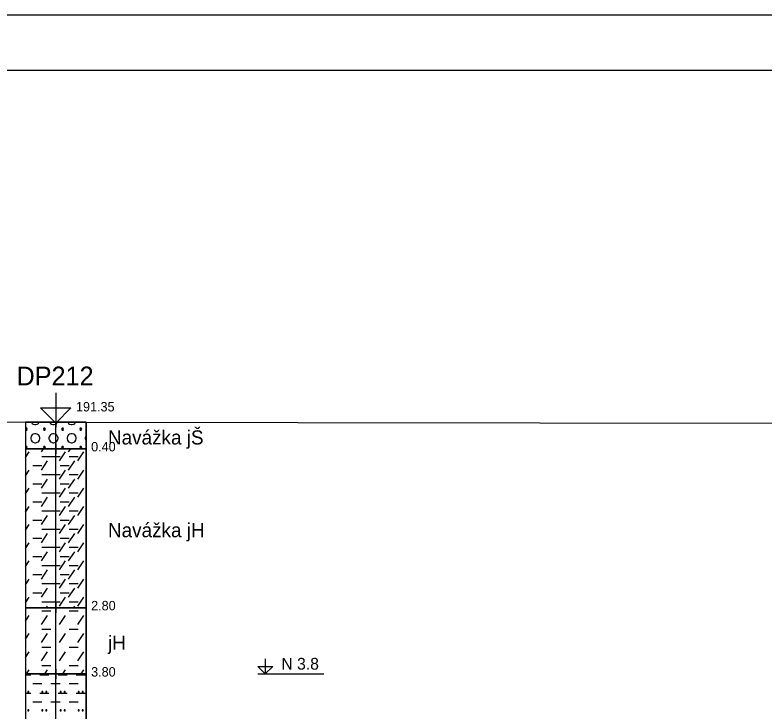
# Model space of a CAD drawing. Extents: x 3042 to 4120, y 576 to 2694.
# Drawn here: x 3879.6 to 3936.1, y 1352.3 to 1404.8 of the extents above; entities that cross this region are included whole.
import ezdxf

# ---------------------------------------------------------------- set-up
doc = ezdxf.new("R2010")
doc.units = 0
for name, color, linetype in [('1', 7, 'Continuous'), ('11', 7, 'Continuous'), ('15', 7, 'Continuous'), ('16', 7, 'Continuous'), ('17', 7, 'Continuous'), ('18', 7, 'Continuous'), ('51', 7, 'Continuous'), ('52', 7, 'Continuous'), ('53', 7, 'Continuous'), ('56', 7, 'Continuous'), ('61', 7, 'Continuous')]:
    doc.layers.add(name, color=color, linetype=linetype)

msp = doc.modelspace()

# ---------------------------------------------------------------- linework, layer by layer
at = {"layer": '1'}
for points in [[(3752.823, 1404.813), (4067.823, 1404.813), (4067.823, 1299.813), (3752.823, 1299.813), (3752.823, 1404.813)], [(3757.014, 1304.004), (4063.632, 1304.004), (4063.632, 1400.622), (3757.014, 1400.622), (3757.014, 1304.004)]]:
    msp.add_lwpolyline(points, dxfattribs=at)
at = {"layer": '11'}
for p, q in [((3831.333, 1374.363), (3882.673, 1374.063)), ((3882.673, 1374.063), (3955.713, 1373.963))]:
    msp.add_line(p, q, dxfattribs=at)
at = {"layer": '15'}
msp.add_lwpolyline([(3882.673, 1376.286), (3882.673, 1374), (3881.53, 1375.143), (3883.816, 1375.143), (3882.673, 1374)], dxfattribs=at)
at = {"layer": '18'}
msp.add_line((3882.673, 1327.313), (3882.673, 1374.063), dxfattribs=at)
at = {"layer": '51'}
for points in [[(3880.387, 1372.063), (3884.959, 1372.063), (3884.959, 1374.063), (3880.387, 1374.063)], [(3880.387, 1360.063), (3884.959, 1360.063), (3884.959, 1372.063), (3880.387, 1372.063)], [(3880.387, 1355.063), (3884.959, 1355.063), (3884.959, 1360.063), (3880.387, 1360.063)], [(3880.387, 1347.063), (3884.959, 1347.063), (3884.959, 1355.063), (3880.387, 1355.063)]]:
    msp.add_lwpolyline(points, close=True, dxfattribs=at)
for points in [[(3880.83, 1374.063), (3880.898, 1373.96), (3880.974, 1373.922), (3881.089, 1373.884), (3881.165, 1373.884), (3881.279, 1373.922), (3881.355, 1373.96), (3881.424, 1374.063)], [(3882.201, 1374.063), (3882.27, 1373.96), (3882.346, 1373.922), (3882.46, 1373.884), (3882.537, 1373.884), (3882.651, 1373.922), (3882.727, 1373.96), (3882.796, 1374.063)], [(3883.573, 1374.063), (3883.641, 1373.96), (3883.718, 1373.922), (3883.832, 1373.884), (3883.908, 1373.884), (3884.022, 1373.922), (3884.099, 1373.96), (3884.167, 1374.063)], [(3880.403, 1373.617), (3880.387, 1373.585)], [(3880.387, 1373.497), (3880.403, 1373.465), (3880.479, 1373.465), (3880.517, 1373.541), (3880.479, 1373.617), (3880.403, 1373.617), (3880.479, 1373.465)], [(3881.089, 1373.198), (3880.974, 1373.16), (3880.898, 1373.122), (3880.822, 1373.008), (3880.784, 1372.893), (3880.784, 1372.817), (3880.822, 1372.703), (3880.898, 1372.589), (3880.974, 1372.55), (3881.089, 1372.512), (3881.165, 1372.512), (3881.279, 1372.55), (3881.355, 1372.589), (3881.432, 1372.703), (3881.47, 1372.817), (3881.47, 1372.893), (3881.432, 1373.008), (3881.355, 1373.122), (3881.279, 1373.16), (3881.165, 1373.198), (3881.089, 1373.198)], [(3881.775, 1373.617), (3881.736, 1373.541), (3881.775, 1373.465), (3881.851, 1373.465), (3881.889, 1373.541), (3881.851, 1373.617), (3881.775, 1373.617), (3881.851, 1373.465)], [(3882.46, 1373.198), (3882.346, 1373.16), (3882.27, 1373.122), (3882.194, 1373.008), (3882.156, 1372.893), (3882.156, 1372.817), (3882.194, 1372.703), (3882.27, 1372.589), (3882.346, 1372.55), (3882.46, 1372.512), (3882.537, 1372.512), (3882.651, 1372.55), (3882.727, 1372.589), (3882.803, 1372.703), (3882.841, 1372.817), (3882.841, 1372.893), (3882.803, 1373.008), (3882.727, 1373.122), (3882.651, 1373.16), (3882.537, 1373.198), (3882.46, 1373.198)], [(3883.146, 1373.617), (3883.108, 1373.541), (3883.146, 1373.465), (3883.222, 1373.465), (3883.26, 1373.541), (3883.222, 1373.617), (3883.146, 1373.617), (3883.222, 1373.465)], [(3883.832, 1373.198), (3883.718, 1373.16), (3883.641, 1373.122), (3883.565, 1373.008), (3883.527, 1372.893), (3883.527, 1372.817), (3883.565, 1372.703), (3883.641, 1372.589), (3883.718, 1372.55), (3883.832, 1372.512), (3883.908, 1372.512), (3884.022, 1372.55), (3884.099, 1372.589), (3884.175, 1372.703), (3884.213, 1372.817), (3884.213, 1372.893), (3884.175, 1373.008), (3884.099, 1373.122), (3884.022, 1373.16), (3883.908, 1373.198), (3883.832, 1373.198)], [(3884.518, 1373.617), (3884.48, 1373.541), (3884.518, 1373.465), (3884.594, 1373.465), (3884.632, 1373.541), (3884.594, 1373.617), (3884.518, 1373.617), (3884.594, 1373.465)], [(3884.959, 1373.041), (3884.937, 1373.008), (3884.899, 1372.893), (3884.899, 1372.817), (3884.937, 1372.703), (3884.959, 1372.67)], [(3880.403, 1372.246), (3880.387, 1372.214)], [(3880.387, 1372.125), (3880.403, 1372.093), (3880.479, 1372.093), (3880.517, 1372.169), (3880.479, 1372.246), (3880.403, 1372.246), (3880.479, 1372.093)], [(3881.584, 1371.827), (3881.742, 1372.063)], [(3881.775, 1372.246), (3881.736, 1372.169), (3881.775, 1372.093), (3881.851, 1372.093), (3881.889, 1372.169), (3881.851, 1372.246), (3881.775, 1372.246), (3881.851, 1372.093)], [(3883.146, 1372.246), (3883.108, 1372.169), (3883.146, 1372.093), (3883.222, 1372.093), (3883.26, 1372.169), (3883.222, 1372.246), (3883.146, 1372.246), (3883.222, 1372.093)], [(3883.641, 1371.827), (3883.799, 1372.063)], [(3884.518, 1372.246), (3884.48, 1372.169), (3884.518, 1372.093), (3884.594, 1372.093), (3884.632, 1372.169), (3884.594, 1372.246), (3884.518, 1372.246), (3884.594, 1372.093)], [(3880.387, 1371.403), (3880.67, 1371.827)], [(3881.622, 1371.484), (3882.308, 1371.484)], [(3882.308, 1371.484), (3882.994, 1371.484)], [(3882.956, 1371.141), (3883.413, 1371.827)], [(3883.68, 1371.484), (3884.365, 1371.484)], [(3884.327, 1371.141), (3884.784, 1371.827)], [(3881.584, 1370.455), (3882.041, 1371.141)], [(3883.641, 1370.455), (3884.099, 1371.141)], [(3880.387, 1370.031), (3880.67, 1370.455)], [(3880.936, 1370.798), (3881.622, 1370.798)], [(3882.956, 1369.769), (3883.413, 1370.455)], [(3882.994, 1370.798), (3883.68, 1370.798)], [(3884.327, 1369.769), (3884.784, 1370.455)], [(3881.584, 1369.083), (3882.041, 1369.769)], [(3881.622, 1370.112), (3882.308, 1370.112)], [(3882.308, 1370.112), (3882.994, 1370.112)], [(3883.641, 1369.083), (3884.099, 1369.769)], [(3883.68, 1370.112), (3884.365, 1370.112)], [(3880.936, 1369.426), (3881.622, 1369.426)], [(3882.994, 1369.426), (3883.68, 1369.426)], [(3880.387, 1368.659), (3880.67, 1369.083)], [(3881.622, 1368.74), (3882.308, 1368.74)], [(3882.308, 1368.74), (3882.994, 1368.74)], [(3882.956, 1368.398), (3883.413, 1369.083)], [(3883.68, 1368.74), (3884.365, 1368.74)], [(3884.327, 1368.398), (3884.784, 1369.083)], [(3880.936, 1368.055), (3881.622, 1368.055)], [(3881.584, 1367.712), (3882.041, 1368.398)], [(3882.994, 1368.055), (3883.68, 1368.055)], [(3883.641, 1367.712), (3884.099, 1368.398)], [(3880.387, 1367.288), (3880.67, 1367.712)], [(3882.956, 1367.026), (3883.413, 1367.712)], [(3884.327, 1367.026), (3884.784, 1367.712)], [(3881.584, 1366.34), (3882.041, 1367.026)], [(3881.622, 1367.369), (3882.308, 1367.369)], [(3882.308, 1367.369), (3882.994, 1367.369)], [(3883.641, 1366.34), (3884.099, 1367.026)], [(3883.68, 1367.369), (3884.365, 1367.369)], [(3880.936, 1366.683), (3881.622, 1366.683)], [(3882.994, 1366.683), (3883.68, 1366.683)], [(3880.387, 1365.916), (3880.67, 1366.34)], [(3881.622, 1365.997), (3882.308, 1365.997)], [(3882.308, 1365.997), (3882.994, 1365.997)], [(3882.956, 1365.654), (3883.413, 1366.34)], [(3883.68, 1365.997), (3884.365, 1365.997)], [(3884.327, 1365.654), (3884.784, 1366.34)], [(3880.936, 1365.311), (3881.622, 1365.311)], [(3881.584, 1364.969), (3882.041, 1365.654)], [(3882.994, 1365.311), (3883.68, 1365.311)], [(3883.641, 1364.969), (3884.099, 1365.654)], [(3880.387, 1364.545), (3880.67, 1364.969)], [(3882.956, 1364.283), (3883.413, 1364.969)], [(3884.327, 1364.283), (3884.784, 1364.969)], [(3881.584, 1363.597), (3882.041, 1364.283)], [(3881.622, 1364.626), (3882.308, 1364.626)], [(3882.308, 1364.626), (3882.994, 1364.626)], [(3883.641, 1363.597), (3884.099, 1364.283)], [(3883.68, 1364.626), (3884.365, 1364.626)], [(3880.387, 1363.173), (3880.67, 1363.597)], [(3880.936, 1363.94), (3881.622, 1363.94)], [(3882.956, 1362.911), (3883.413, 1363.597)], [(3882.994, 1363.94), (3883.68, 1363.94)], [(3884.327, 1362.911), (3884.784, 1363.597)], [(3881.622, 1363.254), (3882.308, 1363.254)], [(3882.308, 1363.254), (3882.994, 1363.254)], [(3883.68, 1363.254), (3884.365, 1363.254)], [(3880.936, 1362.568), (3881.622, 1362.568)], [(3881.584, 1362.225), (3882.041, 1362.911)], [(3882.994, 1362.568), (3883.68, 1362.568)], [(3883.641, 1362.225), (3884.099, 1362.911)], [(3880.387, 1361.801), (3880.67, 1362.225)], [(3881.622, 1361.882), (3882.308, 1361.882)], [(3882.308, 1361.882), (3882.994, 1361.882)], [(3882.956, 1361.54), (3883.413, 1362.225)], [(3883.68, 1361.882), (3884.365, 1361.882)], [(3884.327, 1361.54), (3884.784, 1362.225)], [(3881.584, 1360.854), (3882.041, 1361.54)], [(3883.641, 1360.854), (3884.099, 1361.54)], [(3880.387, 1360.43), (3880.67, 1360.854)], [(3880.936, 1361.197), (3881.622, 1361.197)], [(3882.956, 1360.168), (3883.413, 1360.854)], [(3882.994, 1361.197), (3883.68, 1361.197)], [(3884.327, 1360.168), (3884.784, 1360.854)], [(3881.622, 1360.511), (3882.308, 1360.511)], [(3881.971, 1360.063), (3882.041, 1360.168)], [(3882.308, 1360.511), (3882.994, 1360.511)], [(3883.68, 1360.511), (3884.365, 1360.511)], [(3884.029, 1360.063), (3884.099, 1360.168)], [(3881.622, 1359.825), (3882.308, 1359.825)], [(3883.68, 1359.825), (3884.365, 1359.825)], [(3880.387, 1359.058), (3880.67, 1359.482)], [(3881.584, 1358.796), (3882.041, 1359.482)], [(3882.956, 1358.796), (3883.413, 1359.482)], [(3884.327, 1358.796), (3884.784, 1359.482)], [(3881.622, 1358.453), (3882.308, 1358.453)], [(3883.68, 1358.453), (3884.365, 1358.453)], [(3880.387, 1357.687), (3880.67, 1358.111)], [(3881.584, 1357.425), (3882.041, 1358.111)], [(3882.956, 1357.425), (3883.413, 1358.111)], [(3884.327, 1357.425), (3884.784, 1358.111)], [(3880.387, 1356.315), (3880.67, 1356.739)], [(3881.584, 1356.053), (3882.041, 1356.739)], [(3881.622, 1357.082), (3882.308, 1357.082)], [(3882.956, 1356.053), (3883.413, 1356.739)], [(3883.68, 1357.082), (3884.365, 1357.082)], [(3884.327, 1356.053), (3884.784, 1356.739)], [(3881.622, 1355.71), (3882.308, 1355.71)], [(3883.68, 1355.71), (3884.365, 1355.71)], [(3880.467, 1355.063), (3880.67, 1355.367)], [(3880.555, 1355.063), (3880.555, 1355.024), (3880.632, 1355.024), (3880.632, 1355.063)], [(3880.593, 1355.063), (3880.632, 1355.024)], [(3881.622, 1355.063), (3881.622, 1355.024), (3881.698, 1355.024), (3881.698, 1355.063)], [(3881.66, 1355.063), (3881.698, 1355.024)], [(3881.838, 1355.063), (3882.041, 1355.367)], [(3881.927, 1355.063), (3881.927, 1355.024), (3882.003, 1355.024), (3882.003, 1355.063)], [(3881.965, 1355.063), (3882.003, 1355.024)], [(3882.994, 1355.063), (3882.994, 1355.024), (3883.07, 1355.024), (3883.07, 1355.063)], [(3883.031, 1355.063), (3883.07, 1355.024)], [(3883.21, 1355.063), (3883.413, 1355.367)], [(3883.299, 1355.063), (3883.299, 1355.024), (3883.375, 1355.024), (3883.375, 1355.063)], [(3883.336, 1355.063), (3883.375, 1355.024)], [(3884.365, 1355.063), (3884.365, 1355.024), (3884.442, 1355.024), (3884.442, 1355.063)], [(3884.403, 1355.063), (3884.442, 1355.024)], [(3884.582, 1355.063), (3884.784, 1355.367)], [(3884.67, 1355.063), (3884.67, 1355.024), (3884.746, 1355.024), (3884.746, 1355.063)], [(3884.708, 1355.063), (3884.746, 1355.024)], [(3880.387, 1354.986), (3880.784, 1354.986)], [(3881.47, 1354.986), (3882.156, 1354.986)], [(3882.841, 1354.986), (3883.527, 1354.986)], [(3884.213, 1354.986), (3884.899, 1354.986)], [(3880.936, 1354.339), (3881.622, 1354.339)], [(3882.308, 1354.339), (3882.994, 1354.339)], [(3883.68, 1354.339), (3884.365, 1354.339)], [(3880.387, 1353.615), (3880.784, 1353.615)], [(3880.555, 1353.729), (3880.555, 1353.653), (3880.632, 1353.653), (3880.632, 1353.729), (3880.555, 1353.729), (3880.632, 1353.653)], [(3881.47, 1353.615), (3882.156, 1353.615)], [(3881.622, 1353.729), (3881.622, 1353.653), (3881.698, 1353.653), (3881.698, 1353.729), (3881.622, 1353.729), (3881.698, 1353.653)], [(3881.927, 1353.729), (3881.927, 1353.653), (3882.003, 1353.653), (3882.003, 1353.729), (3881.927, 1353.729), (3882.003, 1353.653)], [(3882.841, 1353.615), (3883.527, 1353.615)], [(3882.994, 1353.729), (3882.994, 1353.653), (3883.07, 1353.653), (3883.07, 1353.729), (3882.994, 1353.729), (3883.07, 1353.653)], [(3883.299, 1353.729), (3883.299, 1353.653), (3883.375, 1353.653), (3883.375, 1353.729), (3883.299, 1353.729), (3883.375, 1353.653)], [(3884.213, 1353.615), (3884.899, 1353.615)], [(3884.365, 1353.729), (3884.365, 1353.653), (3884.442, 1353.653), (3884.442, 1353.729), (3884.365, 1353.729), (3884.442, 1353.653)], [(3884.67, 1353.729), (3884.67, 1353.653), (3884.746, 1353.653), (3884.746, 1353.729), (3884.67, 1353.729), (3884.746, 1353.653)], [(3880.936, 1352.967), (3881.622, 1352.967)], [(3882.308, 1352.967), (3882.994, 1352.967)], [(3883.68, 1352.967), (3884.365, 1352.967)], [(3880.555, 1352.357), (3880.555, 1352.281), (3880.632, 1352.281), (3880.632, 1352.357), (3880.555, 1352.357), (3880.632, 1352.281)], [(3881.622, 1352.357), (3881.622, 1352.281), (3881.698, 1352.281), (3881.698, 1352.357), (3881.622, 1352.357), (3881.698, 1352.281)], [(3881.927, 1352.357), (3881.927, 1352.281), (3882.003, 1352.281), (3882.003, 1352.357), (3881.927, 1352.357), (3882.003, 1352.281)], [(3882.994, 1352.357), (3882.994, 1352.281), (3883.07, 1352.281), (3883.07, 1352.357), (3882.994, 1352.357), (3883.07, 1352.281)], [(3883.299, 1352.357), (3883.299, 1352.281), (3883.375, 1352.281), (3883.375, 1352.357), (3883.299, 1352.357), (3883.375, 1352.281)], [(3884.365, 1352.357), (3884.365, 1352.281), (3884.442, 1352.281), (3884.442, 1352.357), (3884.365, 1352.357), (3884.442, 1352.281)], [(3884.67, 1352.357), (3884.67, 1352.281), (3884.746, 1352.281), (3884.746, 1352.357), (3884.67, 1352.357), (3884.746, 1352.281)]]:
    msp.add_lwpolyline(points, dxfattribs=at)
at = {"layer": '53'}
for points in [[(3880.387, 1374.063), (3884.959, 1374.063)], [(3880.387, 1374.063), (3880.387, 1329.063)], [(3884.959, 1374.063), (3884.959, 1329.063)], [(3880.387, 1372.063), (3884.959, 1372.063)], [(3880.387, 1360.063), (3884.959, 1360.063)], [(3880.387, 1355.063), (3884.959, 1355.063)]]:
    msp.add_lwpolyline(points, dxfattribs=at)
at = {"layer": '56'}
for points in [[(3882.673, 1374.444), (3882.673, 1373.682)], [(3882.292, 1374.063), (3883.054, 1374.063)], [(3882.292, 1372.063), (3883.054, 1372.063)], [(3882.673, 1372.444), (3882.673, 1371.682)], [(3882.673, 1360.444), (3882.673, 1359.682)], [(3882.292, 1360.063), (3883.054, 1360.063)], [(3882.292, 1355.063), (3883.054, 1355.063)], [(3882.673, 1355.444), (3882.673, 1354.682)]]:
    msp.add_lwpolyline(points, dxfattribs=at)
at = {"layer": '61'}
for points in [[(3898.484, 1356.206), (3898.484, 1355.063), (3897.913, 1355.635), (3899.056, 1355.635), (3898.484, 1355.063)], [(3897.913, 1355.063), (3902.908, 1355.063)]]:
    msp.add_lwpolyline(points, dxfattribs=at)

# ---------------------------------------------------------------- texts
at = {"layer": '16'}
msp.add_text('DP212', height=1.4224, dxfattribs=at).set_placement((3879.71, 1376.842))
at = {"layer": '17'}
msp.add_text('191.35', height=0.7112, dxfattribs=at).set_placement((3884.197, 1374.881))
at = {"layer": '52'}
for s, height, p in [('Navážka jŠ', 1.0668, (3886.61, 1372.385)), ('0.40', 0.7112, (3885.34, 1371.865)), ('Navážka jH', 1.0668, (3886.61, 1365.385)), ('2.80', 0.7112, (3885.34, 1359.865)), ('jH', 1.0668, (3886.61, 1356.885)), ('3.80', 0.7112, (3885.34, 1354.865))]:
    msp.add_text(s, height=height, dxfattribs=at).set_placement(p)
at = {"layer": '61'}
msp.add_text('N 3.8', height=0.889, dxfattribs=at).set_placement((3899.691, 1355.387))

doc.saveas('drawing.dxf')
